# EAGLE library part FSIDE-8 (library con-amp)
AMP connector
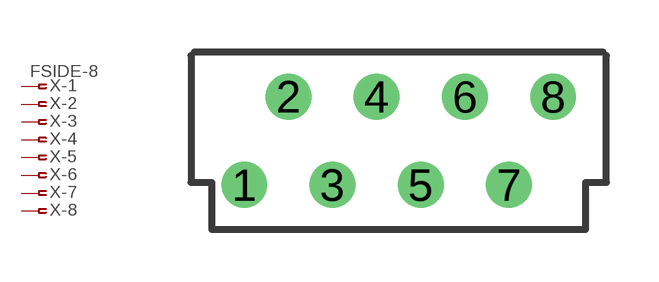
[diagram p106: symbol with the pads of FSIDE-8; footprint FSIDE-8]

Designator prefix X; gates -1=PIN-FV -2=PIN-F -3=PIN-F -4=PIN-F -5=PIN-F -6=PIN-F -7=PIN-F -8=PIN-F

## FSIDE-8 (OC_FARNELL: unknown; OC_NEWARK: unknown)  [FSIDE-8]
1  -1:1  pas
2  -2:1  pas
3  -3:1  pas
4  -4:1  pas
5  -5:1  pas
6  -6:1  pas
7  -7:1  pas
8  -8:1  pas

## Footprint FSIDE-8 (pad centres in mm)
AMP connector
drill 0.813 round: 1 -4.445,-1.27; 2 -3.175,1.27; 3 -1.905,-1.27; 4 -0.635,1.27; 5 0.635,-1.27; 6 1.905,1.27; 7 3.175,-1.27; 8 4.445,1.27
